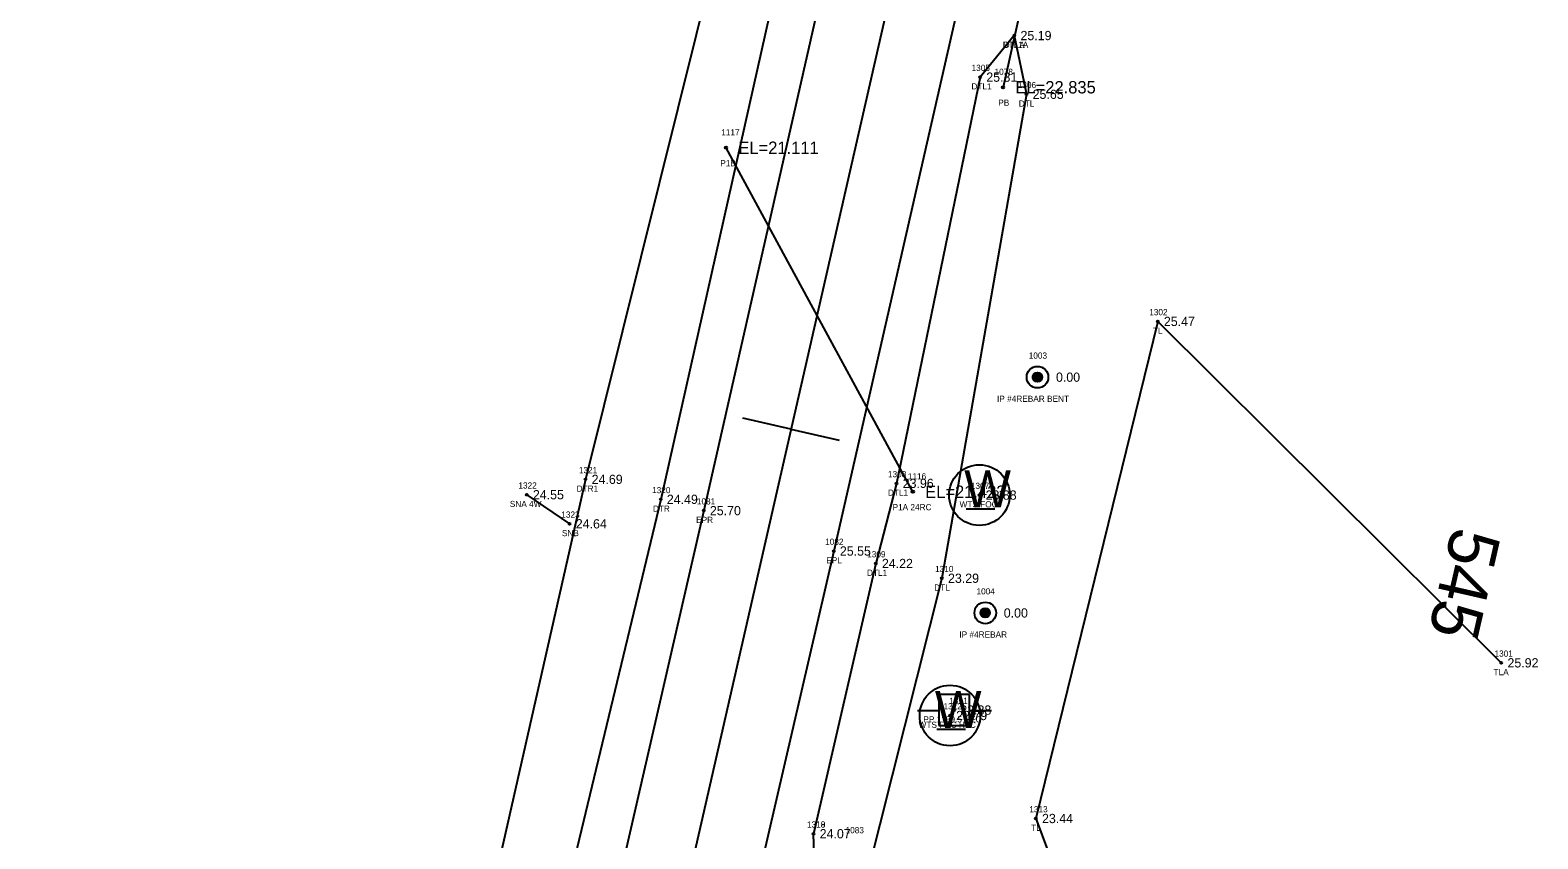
# Model space of a CAD drawing. Extents: x 2654414 to 2656963, y 761776 to 764965.
# Drawn here: x 2655843.9 to 2656088.1, y 764280.4 to 764411.4 of the extents above; entities that cross this region are included whole.
import ezdxf

# ---------------------------------------------------------------- set-up
doc = ezdxf.new("R2010")
doc.units = 0
for name, color, linetype in [('Default', 7, 'Continuous'), ('RD_EX_BldgApp', 7, 'Continuous'), ('RD_EX_BldgApp_txCode', 7, 'Continuous'), ('RD_EX_DR_Pipe', 7, 'Continuous'), ('RD_EX_DR_Pipe_txCode', 7, 'Continuous'), ('RD_EX_DV_Prop_txCode', 7, 'Continuous'), ('RD_EX_DV_PropPin', 7, 'Continuous'), ('RD_EX_H2O', 7, 'Continuous'), ('RD_EX_H2O_txCode', 7, 'Continuous'), ('RD_EX_Road', 7, 'Continuous'), ('RD_EX_Road_txCode', 7, 'Continuous'), ('RD_EX_TX_BldgApp_ELEV', 7, 'Continuous'), ('RD_EX_TX_DV_Prop_ELEV', 7, 'Continuous'), ('RD_EX_TX_H2O_ELEV', 7, 'Continuous'), ('RD_EX_TX_Road_ELEV', 7, 'Continuous'), ('RD_EX_TX_UT_ELEV', 7, 'Continuous'), ('RD_EX_TX_VEG_ELEV', 7, 'Continuous'), ('RD_EX_UT', 7, 'Continuous'), ('RD_EX_UT_txCode', 7, 'Continuous'), ('RD_EX_VEG', 7, 'Continuous'), ('RD_EX_VEG_txCode', 7, 'Continuous'), ('RD_HC_Cl', 7, 'Continuous'), ('RD_HC_Data_Tic', 7, 'Continuous'), ('RD_HC_Survey_ELEV', 7, 'Continuous'), ('RD_HC_TX_Sta50', 7, 'Continuous'), ('RD_SMD_Locator', 7, 'Continuous'), ('RD_TX_Pipe_ElevEX', 7, 'Continuous')]:
    doc.layers.add(name, color=color, linetype=linetype)

msp = doc.modelspace()

# ---------------------------------------------------------------- linework, layer by layer
at = {"layer": 'Default'}
msp.add_line((2656050.51, 764712.37), (2655383.26, 761787.51), dxfattribs=at)
at = {"layer": 'RD_EX_BldgApp'}
msp.add_line((2655924.3, 764336.15), (2655931.25, 764331.43), dxfattribs=at)
at = {"layer": 'RD_EX_DR_Pipe'}
for p, q in [((2656020.76, 764488.83), (2656001.47, 764402.19)), ((2655986.85, 764336.63), (2655956.59, 764392.39))]:
    msp.add_line(p, q, dxfattribs=at)
at = {"layer": 'RD_EX_DV_PropPin'}
for p, q in [((2656006.31, 764355), (2656006.31, 764355.39)), ((2656006.34, 764354.9), (2656006.34, 764355.49)), ((2656006.38, 764354.83), (2656006.38, 764355.57)), ((2656006.41, 764354.77), (2656006.41, 764355.62)), ((2656006.45, 764354.72), (2656006.45, 764355.67)), ((2656006.48, 764354.68), (2656006.48, 764355.71)), ((2656006.52, 764354.65), (2656006.52, 764355.75)), ((2656006.55, 764354.61), (2656006.55, 764355.78)), ((2656006.59, 764354.59), (2656006.59, 764355.81)), ((2656006.62, 764354.56), (2656006.62, 764355.83)), ((2656006.66, 764354.54), (2656006.66, 764355.85)), ((2656006.69, 764354.52), (2656006.69, 764355.87)), ((2656006.73, 764354.5), (2656006.73, 764355.89)), ((2656006.76, 764354.49), (2656006.76, 764355.9)), ((2656006.8, 764354.48), (2656006.8, 764355.92)), ((2656006.83, 764354.47), (2656006.83, 764355.93)), ((2656006.87, 764354.46), (2656006.87, 764355.94)), ((2656006.9, 764354.45), (2656006.9, 764355.94)), ((2656006.94, 764354.44), (2656006.94, 764355.95)), ((2656006.97, 764354.44), (2656006.97, 764355.95)), ((2656007.01, 764354.44), (2656007.01, 764355.96)), ((2656007.04, 764354.44), (2656007.04, 764355.96)), ((2656007.08, 764354.44), (2656007.08, 764355.96)), ((2656007.11, 764354.44), (2656007.11, 764355.95)), ((2656007.15, 764354.44), (2656007.15, 764355.95)), ((2656007.18, 764354.45), (2656007.18, 764355.94)), ((2656007.22, 764354.46), (2656007.22, 764355.94)), ((2656007.25, 764354.47), (2656007.25, 764355.93)), ((2656007.29, 764354.48), (2656007.29, 764355.92)), ((2656007.32, 764354.49), (2656007.32, 764355.9)), ((2656007.36, 764354.5), (2656007.36, 764355.89)), ((2656007.39, 764354.52), (2656007.39, 764355.87)), ((2656007.43, 764354.54), (2656007.43, 764355.85)), ((2656007.46, 764354.56), (2656007.46, 764355.83)), ((2656007.5, 764354.59), (2656007.5, 764355.81)), ((2656007.53, 764354.61), (2656007.53, 764355.78)), ((2656007.57, 764354.65), (2656007.57, 764355.75)), ((2656007.6, 764354.68), (2656007.6, 764355.71)), ((2656007.64, 764354.72), (2656007.64, 764355.67)), ((2656007.67, 764354.77), (2656007.67, 764355.62)), ((2656007.71, 764354.83), (2656007.71, 764355.57)), ((2656007.74, 764354.9), (2656007.74, 764355.49)), ((2656007.78, 764355), (2656007.78, 764355.39)), ((2655997.85, 764316.8), (2655997.85, 764317.19)), ((2655997.88, 764316.7), (2655997.88, 764317.29)), ((2655997.92, 764316.62), (2655997.92, 764317.36)), ((2655997.95, 764316.57), (2655997.95, 764317.42)), ((2655997.99, 764316.52), (2655997.99, 764317.47)), ((2655998.02, 764316.48), (2655998.02, 764317.51)), ((2655998.06, 764316.44), (2655998.06, 764317.55)), ((2655998.09, 764316.41), (2655998.09, 764317.58)), ((2655998.13, 764316.38), (2655998.13, 764317.6)), ((2655998.16, 764316.36), (2655998.16, 764317.63)), ((2655998.2, 764316.34), (2655998.2, 764317.65)), ((2655998.23, 764316.32), (2655998.23, 764317.67)), ((2655998.27, 764316.3), (2655998.27, 764317.69)), ((2655998.3, 764316.29), (2655998.3, 764317.7)), ((2655998.34, 764316.27), (2655998.34, 764317.71)), ((2655998.37, 764316.26), (2655998.37, 764317.73)), ((2655998.41, 764316.25), (2655998.41, 764317.74)), ((2655998.44, 764316.25), (2655998.44, 764317.74)), ((2655998.48, 764316.24), (2655998.48, 764317.75)), ((2655998.51, 764316.24), (2655998.51, 764317.75)), ((2655998.55, 764316.23), (2655998.55, 764317.75)), ((2655998.58, 764316.23), (2655998.58, 764317.76)), ((2655998.62, 764316.23), (2655998.62, 764317.75)), ((2655998.65, 764316.24), (2655998.65, 764317.75)), ((2655998.69, 764316.24), (2655998.69, 764317.75)), ((2655998.72, 764316.25), (2655998.72, 764317.74)), ((2655998.76, 764316.25), (2655998.76, 764317.74)), ((2655998.79, 764316.26), (2655998.79, 764317.73)), ((2655998.83, 764316.27), (2655998.83, 764317.71)), ((2655998.86, 764316.29), (2655998.86, 764317.7)), ((2655998.9, 764316.3), (2655998.9, 764317.69)), ((2655998.93, 764316.32), (2655998.93, 764317.67)), ((2655998.97, 764316.34), (2655998.97, 764317.65)), ((2655999, 764316.36), (2655999, 764317.63)), ((2655999.04, 764316.38), (2655999.04, 764317.6)), ((2655999.07, 764316.41), (2655999.07, 764317.58)), ((2655999.11, 764316.44), (2655999.11, 764317.55)), ((2655999.14, 764316.48), (2655999.14, 764317.51)), ((2655999.18, 764316.52), (2655999.18, 764317.47)), ((2655999.21, 764316.57), (2655999.21, 764317.42)), ((2655999.25, 764316.62), (2655999.25, 764317.36)), ((2655999.28, 764316.7), (2655999.28, 764317.29)), ((2655999.32, 764316.8), (2655999.32, 764317.19))]:
    msp.add_line(p, q, dxfattribs=at)
for centre, radius in [((2656007.04, 764355.2), 1.75), ((2656007.04, 764355.2), 0.761), ((2655998.58, 764316.99), 1.75), ((2655998.58, 764316.99), 0.761)]:
    msp.add_circle(centre, radius, dxfattribs=at)
at = {"layer": 'RD_EX_H2O'}
for points in [[(2655985.99, 764532.58), (2655990.84, 764527.53), (2655967.74, 764432.27), (2655946, 764335.4), (2655922.66, 764238.07), (2655902.06, 764145.42), (2655879.59, 764053.25), (2655859.1, 763959.14), (2655841.15, 763874.16), (2655837.57, 763865.39), (2655829.11, 763865.29), (2655761.29, 763886.78)], [(2655985.99, 764532.58), (2655980.45, 764530.42), (2655978.53, 764524.06), (2655957.73, 764434.81), (2655933.82, 764338.64), (2655911.79, 764241.24), (2655890.59, 764146.77), (2655869.91, 764054.39), (2655847.97, 763961.11)], [(2656003.29, 764410.57), (2655997.75, 764403.83), (2655984.21, 764337.99), (2655980.84, 764325), (2655970.76, 764281.2)], [(2656003.29, 764410.57), (2656005.26, 764401.05), (2655991.55, 764322.61), (2655977.47, 764266.58), (2655971.19, 764268.14), (2655970.76, 764281.2)]]:
    msp.add_lwpolyline(points, dxfattribs=at)
at = {"layer": 'RD_EX_Road'}
for points in [[(2656041.72, 764723.31), (2656018.5, 764622.03), (2656002.75, 764552.49), (2655997.43, 764530.02), (2655974.74, 764429.64), (2655952.97, 764333.57), (2655930.52, 764235.7), (2655909.18, 764142.93), (2655887.93, 764050.57), (2655866.91, 763957.26), (2655846.82, 763869.53), (2655845.21, 763862.22), (2655839.99, 763839.71), (2655823.38, 763766.66), (2655801.33, 763669.93), (2655780.03, 763576.53), (2655774.26, 763551.85), (2655771.37, 763539.86), (2655759.09, 763486.9), (2655736.94, 763391.72), (2655715.19, 763296.77), (2655711.35, 763278.45)], [(2656062.87, 764717.57), (2656039.84, 764617.04), (2656035.41, 764597.94), (2656033.38, 764589.18), (2656018.27, 764522.6), (2656017.22, 764517.64), (2656011.07, 764490.22), (2655996.52, 764425.63), (2655974.03, 764327.02), (2655960.71, 764269.34), (2655951.96, 764231.59), (2655930.84, 764138.62), (2655926.81, 764121.01), (2655909.26, 764045.26), (2655908.15, 764039.87), (2655902.08, 764013.51), (2655888.19, 763952.26), (2655880.73, 763919.6), (2655875, 763893.73), (2655866.73, 763857), (2655852.89, 763796.34), (2655850.73, 763786.52)]]:
    msp.add_lwpolyline(points, dxfattribs=at)
at = {"layer": 'RD_EX_UT'}
for p, q in [((2655995.51, 764333.88), (2656000.14, 764333.88)), ((2655996.04, 764303.75), (2655991.04, 764303.75)), ((2655991.04, 764303.75), (2655991.04, 764298.75)), ((2655996.04, 764298.75), (2655996.04, 764303.75)), ((2655987.6, 764301.19), (2655991.07, 764301.19)), ((2655995.96, 764301.19), (2655999.6, 764301.19)), ((2655990.74, 764298.15), (2655995.37, 764298.15)), ((2655991.04, 764298.75), (2655996.04, 764298.75))]:
    msp.add_line(p, q, dxfattribs=at)
for centre in [(2655997.63, 764336.09), (2655992.87, 764300.36)]:
    msp.add_circle(centre, 4.91, dxfattribs=at)
at = {"layer": 'RD_EX_VEG'}
msp.add_lwpolyline([(2656082.18, 764308.9), (2656026.52, 764364.24), (2656006.78, 764283.67), (2656021.32, 764244.65), (2656065.22, 764210.86)], dxfattribs=at)
at = {"layer": 'RD_HC_Cl'}
msp.add_line((2656050.51, 764712.37), (2655383.26, 761787.51), dxfattribs=at)
at = {"layer": 'RD_HC_Data_Tic'}
for q in [(2655959.3, 764348.54), (2655974.9, 764344.98)]:
    msp.add_line((2655967.1, 764346.76), q, dxfattribs=at)
at = {"layer": 'RD_SMD_Locator'}
for centre, radius in [((2656003.29, 764410.57), 0.15), ((2656003.29, 764410.57), 0.15), ((2655997.75, 764403.83), 0.15), ((2656001.47, 764402.19), 0.2), ((2656005.26, 764401.05), 0.15), ((2655956.59, 764392.39), 0.2), ((2656026.52, 764364.24), 0.15), ((2656007.04, 764355.2), 0.15), ((2655933.82, 764338.64), 0.15), ((2655984.21, 764337.99), 0.15), ((2655986.85, 764336.63), 0.2), ((2655924.3, 764336.15), 0.15), ((2655946, 764335.4), 0.15), ((2655997.63, 764336.09), 0.15), ((2655952.97, 764333.57), 0.15), ((2655931.25, 764331.43), 0.15), ((2655974.03, 764327.02), 0.15), ((2655980.84, 764325), 0.15), ((2655991.55, 764322.61), 0.15), ((2655998.58, 764316.99), 0.15), ((2656082.18, 764308.9), 0.15), ((2655992.87, 764300.36), 0.15), ((2655993.54, 764301.24), 0.15), ((2656006.78, 764283.67), 0.15), ((2655970.76, 764281.2), 0.15), ((2655970.76, 764281.2), 0.15)]:
    msp.add_circle(centre, radius, dxfattribs=at)

# ---------------------------------------------------------------- texts
at = {"layer": 'RD_EX_BldgApp_txCode'}
for s, p in [('1322', (2655922.95, 764337.15)), ('SNA 4W', (2655921.56, 764334.15)), ('1323', (2655929.9, 764332.43)), ('SNB', (2655930, 764329.43))]:
    msp.add_text(s, height=1, dxfattribs=at).set_placement(p)
at = {"layer": 'RD_EX_DR_Pipe_txCode'}
for s, p in [('1078', (2656000.08, 764404.19)), ('PB', (2656000.69, 764399.19)), ('1117', (2655955.81, 764394.39)), ('P1B', (2655955.65, 764389.39)), ('1116', (2655986.04, 764338.63)), ('P1A 24RC', (2655983.56, 764333.63)), ('1083', (2655975.95, 764281.28))]:
    msp.add_text(s, height=1, dxfattribs=at).set_placement(p)
at = {"layer": 'RD_EX_DV_Prop_txCode'}
for s, p in [('1003', (2656005.62, 764358.2)), ('IP #4REBAR BENT', (2656000.49, 764351.2)), ('1004', (2655997.16, 764319.99)), ('IP #4REBAR', (2655994.39, 764312.99))]:
    msp.add_text(s, height=1, dxfattribs=at).set_placement(p)
at = {"layer": 'RD_EX_H2O_txCode'}
for s, p in [('DTL1A', (2656001.39, 764408.57)), ('DTLA', (2656001.56, 764408.57)), ('1305', (2655996.36, 764404.83)), ('DTL1', (2655996.34, 764401.83)), ('1306', (2656003.85, 764402.05)), ('DTL', (2656004.01, 764399.05)), ('1321', (2655932.75, 764339.64)), ('1308', (2655982.82, 764338.99)), ('DTR1', (2655932.38, 764336.64)), ('1320', (2655944.61, 764336.4)), ('DTL1', (2655982.8, 764335.99)), ('DTR', (2655944.73, 764333.4)), ('1309', (2655979.45, 764326)), ('1310', (2655990.45, 764323.61)), ('DTL1', (2655979.43, 764323)), ('DTL', (2655990.31, 764320.61)), ('1318', (2655969.7, 764282.2)), ('1319', (2655969.7, 764282.2))]:
    msp.add_text(s, height=1, dxfattribs=at).set_placement(p)
at = {"layer": 'RD_EX_Road_txCode'}
for s, p in [('1081', (2655951.86, 764334.57)), ('EPR', (2655951.74, 764331.57)), ('1082', (2655972.64, 764328.02)), ('EPL', (2655972.82, 764325.02))]:
    msp.add_text(s, height=1, dxfattribs=at).set_placement(p)
at = {"layer": 'RD_EX_TX_BldgApp_ELEV'}
for s, p in [('24.55', (2655925.3, 764335.4)), ('24.64', (2655932.25, 764330.68))]:
    msp.add_text(s, height=1.5, dxfattribs=at).set_placement(p)
at = {"layer": 'RD_EX_TX_DV_Prop_ELEV'}
for p in [(2656010.04, 764354.45), (2656001.58, 764316.24)]:
    msp.add_text('0.00', height=1.5, dxfattribs=at).set_placement(p)
at = {"layer": 'RD_EX_TX_H2O_ELEV'}
for s, p in [('25.19', (2656004.29, 764409.82)), ('25.19', (2656004.29, 764409.82)), ('25.31', (2655998.75, 764403.08)), ('25.65', (2656006.26, 764400.3)), ('24.69', (2655934.82, 764337.89)), ('23.96', (2655985.21, 764337.24)), ('24.49', (2655947, 764334.65)), ('24.22', (2655981.84, 764324.25)), ('23.29', (2655992.55, 764321.86)), ('24.07', (2655971.76, 764280.45)), ('24.07', (2655971.76, 764280.45))]:
    msp.add_text(s, height=1.5, dxfattribs=at).set_placement(p)
at = {"layer": 'RD_EX_TX_Road_ELEV'}
for s, p in [('25.70', (2655953.97, 764332.82)), ('25.55', (2655975.03, 764326.27))]:
    msp.add_text(s, height=1.5, dxfattribs=at).set_placement(p)
at = {"layer": 'RD_EX_TX_UT_ELEV'}
for s, p in [('23.88', (2655998.64, 764335.34)), ('22.79', (2655993.87, 764299.61))]:
    msp.add_text(s, height=1.5, dxfattribs=at).set_placement(p)
at = {"layer": 'RD_EX_TX_VEG_ELEV'}
for s, p in [('25.47', (2656027.52, 764363.49)), ('25.92', (2656083.18, 764308.15)), ('23.44', (2656007.78, 764282.92))]:
    msp.add_text(s, height=1.5, dxfattribs=at).set_placement(p)
at = {"layer": 'RD_EX_UT'}
for p in [(2655995.17, 764334.09), (2655990.41, 764298.35)]:
    msp.add_text('W', height=6, dxfattribs=at).set_placement(p)
at = {"layer": 'RD_EX_UT_txCode'}
for s, p in [('1307', (2655996.25, 764337.09)), ('WTS FOC', (2655994.42, 764334.09)), ('1312', (2655991.81, 764301.36)), ('1311', (2655992.76, 764302.24)), ('PP 1159.5 HEC', (2655988.55, 764299.24)), ('WTS FOC HTC', (2655987.78, 764298.36))]:
    msp.add_text(s, height=1, dxfattribs=at).set_placement(p)
at = {"layer": 'RD_EX_VEG_txCode'}
for s, p in [('1302', (2656025.14, 764365.24)), ('TL', (2656025.75, 764362.24)), ('1301', (2656081.08, 764309.9)), ('TLA', (2656080.92, 764306.9)), ('1313', (2656005.72, 764284.67)), ('TL', (2656006.01, 764281.67))]:
    msp.add_text(s, height=1, dxfattribs=at).set_placement(p)
at = {"layer": 'RD_HC_Survey_ELEV'}
msp.add_text('22.88', height=1.5, dxfattribs=at).set_placement((2655994.54, 764300.49))
at = {"layer": 'RD_HC_TX_Sta50'}
msp.add_text('545', height=8, rotation=257.149, dxfattribs=at).set_placement((2656074.33, 764331.22))
at = {"layer": 'RD_TX_Pipe_ElevEX'}
for s, p in [('EL=22.835', (2656003.47, 764401.19)), ('EL=21.111', (2655958.59, 764391.39)), ('EL=21.423', (2655988.85, 764335.63))]:
    msp.add_text(s, height=2, dxfattribs=at).set_placement(p)

doc.saveas('drawing.dxf')
